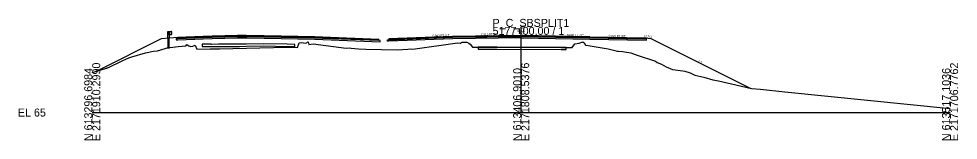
# Model space of a CAD drawing. Extents: x -26 to 1303, y -3010 to 12023.
# Drawn here: x -25.7 to 302.8, y 2990.3 to 3032.8 of the extents above; entities that cross this region are included whole.
import ezdxf

# ---------------------------------------------------------------- set-up
doc = ezdxf.new("R2010")
doc.units = 0
for name, color, linetype in [('RD_GPK_XS_Cell', 7, 'Continuous'), ('RD_PD_Final_TrvlWay', 7, 'Continuous'), ('RD_XS_Base', 7, 'Continuous'), ('RD_XS_ExGround', 7, 'Continuous'), ('RD_XS_ExPaveRet', 7, 'Continuous'), ('RD_XS_GR', 7, 'Continuous'), ('RD_XS_Greenside', 7, 'Continuous'), ('RD_XS_Pave', 7, 'Continuous'), ('RD_XS_PaveOvlay_CP', 7, 'Continuous'), ('RD_XS_TieSlope', 7, 'Continuous'), ('RD_XS_TX_Elev_EX', 7, 'Continuous'), ('RD_XS_TX_Elev_PR', 7, 'Continuous'), ('RD_XS_TX_ShdSlope', 7, 'Continuous'), ('RD_XS_TX_Slope', 7, 'Continuous')]:
    doc.layers.add(name, color=color, linetype=linetype)

msp = doc.modelspace()

# ---------------------------------------------------------------- linework, layer by layer
at = {"layer": 'RD_GPK_XS_Cell'}
for p, q in [((150, 3000), (150, 3030)), ((0, 3000), (150, 3000)), ((150, 3000), (300, 3000))]:
    msp.add_line(p, q, dxfattribs=at)
at = {"layer": 'RD_PD_Final_TrvlWay'}
for p, q in [((26.94, 3026.03), (26.44, 3025.99)), ((26.44, 3025.99), (26.44, 3022.43)), ((26.94, 3022.43), (26.94, 3026.03))]:
    msp.add_line(p, q, dxfattribs=at)
at = {"layer": 'RD_XS_Base'}
for p, q in [((29.75, 3025.95), (29.38, 3025.93)), ((29.38, 3025.93), (29.38, 3025.8)), ((29.38, 3025.8), (29.38, 3025.43)), ((29.88, 3025.95), (29.75, 3025.95)), ((38.75, 3026.31), (29.88, 3025.95)), ((29.88, 3025.45), (38.75, 3025.81)), ((41.88, 3026.43), (38.75, 3026.31)), ((38.75, 3025.81), (41.88, 3025.93)), ((50.75, 3026.61), (41.88, 3026.43)), ((41.88, 3025.93), (50.75, 3026.11)), ((53.88, 3026.67), (50.75, 3026.61)), ((50.75, 3026.11), (53.88, 3026.17)), ((53.88, 3026.79), (53.88, 3026.83)), ((53.88, 3026.83), (53.88, 3026.66)), ((53.88, 3026.67), (53.88, 3026.79)), ((53.88, 3026.54), (53.88, 3026.67)), ((60.14, 3026.55), (53.88, 3026.67)), ((53.88, 3026.66), (53.88, 3026.17)), ((53.88, 3026.17), (53.88, 3026.54)), ((53.88, 3026.17), (60.14, 3026.05)), ((77.88, 3026.19), (60.14, 3026.55)), ((60.14, 3026.05), (77.88, 3025.69)), ((80.49, 3026.09), (77.88, 3026.19)), ((100.21, 3025.3), (80.49, 3026.09)), ((103.74, 3025.46), (126, 3026.35)), ((126, 3025.85), (103.74, 3024.96)), ((126, 3026.35), (150.01, 3026.66)), ((126, 3026.35), (126, 3026.35)), ((150.01, 3026.16), (126, 3025.85)), ((126, 3025.85), (126, 3025.85)), ((150, 3026.66), (150, 3026.82)), ((150, 3026.82), (150, 3026.82)), ((150, 3026.82), (150, 3026.82)), ((150, 3026.82), (150, 3026.16)), ((150, 3026.66), (150, 3026.66)), ((162, 3026.42), (150, 3026.66)), ((150, 3026.66), (150, 3026.66)), ((150, 3026.66), (150, 3026.16)), ((150, 3026.16), (150, 3026.16)), ((150, 3026.16), (162, 3025.92)), ((174, 3026.18), (162, 3026.42)), ((162, 3026.42), (162, 3026.42)), ((162, 3025.92), (162, 3025.92)), ((162, 3025.92), (174, 3025.68)), ((193.3, 3025.8), (174, 3026.18)), ((174, 3026.18), (174, 3026.18)), ((193.8, 3025.79), (193.3, 3025.8)), ((193.3, 3025.8), (193.3, 3025.8)), ((193.8, 3025.29), (193.8, 3025.79)), ((193.8, 3025.79), (193.8, 3025.79)), ((29.38, 3025.43), (29.75, 3025.45)), ((29.75, 3025.45), (29.88, 3025.45)), ((77.88, 3025.69), (80.62, 3025.58)), ((80.62, 3025.58), (100.71, 3024.78)), ((100.34, 3025.29), (100.21, 3025.3)), ((100.71, 3025.28), (100.34, 3025.29)), ((100.71, 3025.15), (100.71, 3025.28)), ((100.71, 3024.78), (100.71, 3025.15)), ((103.24, 3025.44), (103.74, 3025.46)), ((103.24, 3024.94), (103.24, 3025.44)), ((103.24, 3025.44), (103.24, 3025.44)), ((103.74, 3024.96), (103.24, 3024.94)), ((103.24, 3024.94), (103.24, 3024.94)), ((103.24, 3024.94), (103.24, 3024.94)), ((103.74, 3025.46), (103.74, 3025.46)), ((103.74, 3024.96), (103.74, 3024.96)), ((174, 3025.68), (174, 3025.68)), ((174, 3025.68), (193.8, 3025.29))]:
    msp.add_line(p, q, dxfattribs=at)
at = {"layer": 'RD_XS_ExGround'}
msp.add_lwpolyline([(0, 3014.08), (4.65, 3015.43), (5.02, 3015.52), (5.09, 3015.55), (5.24, 3015.64), (5.45, 3015.7), (10.75, 3018.23), (12.84, 3019.16), (13.52, 3019.4), (13.83, 3019.51), (18.57, 3020.96), (21.41, 3021.47), (22.76, 3021.64), (25.49, 3022.44), (26.17, 3022.68), (29.08, 3023.06), (30.02, 3023.11), (32.83, 3023.34), (32.86, 3023.46), (33.13, 3023.79), (33.77, 3023.4), (34.47, 3023.08), (35.18, 3023.19), (36, 3023.59), (36.62, 3022.23), (41.25, 3022.34), (42.12, 3022.34), (44.54, 3022.33), (68.1, 3022.92), (70.89, 3022.85), (71.83, 3022.83), (72.33, 3024.47), (73.09, 3024.48), (74.65, 3024.34), (75.55, 3024.74), (75.74, 3023.81), (77.2, 3024.04), (88.77, 3022.6), (89.85, 3022.63), (90.6, 3022.54), (93.1, 3022.37), (95.69, 3022.14), (106.62, 3021.94), (110.36, 3022.15), (111.14, 3022.26), (112.1, 3022.21), (127.78, 3024.42), (128.61, 3024.35), (128.77, 3024.35), (128.81, 3024.35), (128.9, 3024.29), (129.14, 3024.56), (129.34, 3024.63), (129.75, 3024.66), (130.95, 3024.6), (131.42, 3024.43), (131.67, 3024.26), (132.14, 3023.93), (132.94, 3022.95), (137.76, 3022.92), (138.6, 3022.93), (141.57, 3022.95), (163.96, 3022.81), (167, 3022.82), (167.86, 3022.82), (168.77, 3024.11), (170.33, 3024.26), (171.51, 3024.8), (171.98, 3024.45), (172.52, 3023.57), (173.46, 3023.52), (180.45, 3022.3), (183.74, 3021.55), (184.04, 3021.55), (185.38, 3021.41), (186.08, 3021.22), (188.35, 3020.92), (190.59, 3020.13), (197.03, 3017.94), (197.58, 3017.53), (199.12, 3016.94), (200.7, 3015.96), (202.93, 3015.05), (206.5, 3014.58), (207.28, 3014.53), (209.12, 3013.9), (210.7, 3013.13), (213.87, 3012.43), (217.03, 3011.47), (219.03, 3011.05), (220.5, 3010.76), (223.51, 3010.03), (230.53, 3008.47), (233.64, 3008.15), (242.25, 3007.29), (300, 3001.43)], dxfattribs=at)
at = {"layer": 'RD_XS_ExPaveRet'}
for points in [[(68.2, 3023.92), (59.95, 3024.11), (53.83, 3023.96), (51.54, 3023.91), (44.1, 3023.92), (41.81, 3023.86), (41.61, 3023.92), (38.92, 3023.92), (38.47, 3023.91), (38.47, 3023.37), (38.47, 3023.16), (38.92, 3023.17), (41.61, 3023.17), (41.81, 3023.11), (44.1, 3023.17), (51.54, 3023.16), (53.83, 3023.21), (59.95, 3023.36), (68.2, 3023.17), (70.85, 3023.11), (70.85, 3023.32), (70.85, 3023.86), (68.2, 3023.92)], [(68.2, 3023.92), (59.95, 3024.11), (53.83, 3023.96), (51.54, 3023.91), (44.1, 3023.92), (41.81, 3023.86), (41.61, 3023.92), (38.92, 3023.92), (38.47, 3023.91), (38.47, 3023.37), (38.47, 3023.16), (38.92, 3023.17), (41.61, 3023.17), (41.81, 3023.11), (44.1, 3023.17), (51.54, 3023.16), (53.83, 3023.21), (59.95, 3023.36), (68.2, 3023.17), (70.85, 3023.11), (70.85, 3023.32), (70.85, 3023.86), (68.2, 3023.92)], [(163.96, 3022.81), (163.96, 3022.81), (141.57, 3022.95), (141.57, 3022.95), (141.57, 3022.95), (138.6, 3022.93), (137.76, 3022.92), (137.76, 3022.92), (134.92, 3022.94), (134.92, 3022.94), (134.92, 3022.94), (134.92, 3022.19), (134.92, 3022.19), (137.76, 3022.17), (137.76, 3022.17), (138.6, 3022.18), (141.57, 3022.2), (141.57, 3022.2), (141.57, 3022.2), (163.96, 3022.06), (163.96, 3022.06), (163.96, 3022.06), (165.68, 3022.07), (165.68, 3022.82), (165.68, 3022.82), (163.96, 3022.81), (163.96, 3022.81)], [(163.96, 3022.81), (141.57, 3022.95), (138.6, 3022.93), (137.76, 3022.92), (134.92, 3022.94), (134.92, 3022.19), (137.76, 3022.17), (138.6, 3022.18), (141.57, 3022.2), (163.96, 3022.06), (165.68, 3022.07), (165.68, 3022.82), (163.96, 3022.81)]]:
    msp.add_lwpolyline(points, dxfattribs=at)
at = {"layer": 'RD_XS_GR'}
for p, q in [((26.44, 3025.99), (26.44, 3028.43)), ((26.44, 3028.43), (26.69, 3028.43)), ((26.94, 3026.03), (26.44, 3025.99)), ((26.69, 3028.43), (26.94, 3028.43)), ((26.94, 3028.43), (26.94, 3026.03)), ((26.94, 3027.26), (26.94, 3028.43)), ((26.94, 3028.43), (27.61, 3028.43)), ((27.61, 3027.26), (26.94, 3027.26)), ((27.61, 3028.43), (27.61, 3027.26)), ((27.68, 3028.35), (27.61, 3028.43)), ((27.61, 3028.43), (27.61, 3028.12)), ((27.61, 3028.12), (27.61, 3027.26)), ((27.61, 3027.85), (27.81, 3028.06)), ((27.68, 3027.77), (27.61, 3027.85)), ((27.61, 3027.26), (27.81, 3027.48)), ((27.88, 3028.14), (27.68, 3028.35)), ((27.88, 3027.55), (27.68, 3027.77)), ((27.81, 3028.06), (27.88, 3028.14)), ((27.81, 3027.48), (27.88, 3027.55))]:
    msp.add_line(p, q, dxfattribs=at)
at = {"layer": 'RD_XS_Greenside'}
for p, q in [((24.13, 3025.81), (1.59, 3014.54)), ((195.3, 3025.96), (230.08, 3008.56))]:
    msp.add_line(p, q, dxfattribs=at)
at = {"layer": 'RD_XS_Pave'}
for p, q in [((38.75, 3026.62), (29.88, 3026.27)), ((38.75, 3026.46), (29.88, 3026.11)), ((29.88, 3026.11), (38.75, 3026.46)), ((29.88, 3025.95), (38.75, 3026.31)), ((29.88, 3026.27), (29.88, 3026.23)), ((29.88, 3026.23), (29.88, 3026.11)), ((29.88, 3026.11), (29.88, 3026.07)), ((29.88, 3026.07), (29.88, 3025.95)), ((41.88, 3026.75), (38.75, 3026.62)), ((41.88, 3026.59), (38.75, 3026.46)), ((38.75, 3026.46), (41.88, 3026.59)), ((38.75, 3026.31), (41.88, 3026.43)), ((50.75, 3026.93), (41.88, 3026.75)), ((50.75, 3026.77), (41.88, 3026.59)), ((41.88, 3026.59), (50.75, 3026.77)), ((41.88, 3026.43), (50.75, 3026.61)), ((53.88, 3026.99), (50.75, 3026.93)), ((53.88, 3026.83), (50.75, 3026.77)), ((50.75, 3026.77), (53.88, 3026.83)), ((50.75, 3026.61), (53.88, 3026.67)), ((60.14, 3026.86), (53.88, 3026.99)), ((53.88, 3026.79), (53.88, 3026.83)), ((53.88, 3026.83), (60.14, 3026.7)), ((60.14, 3026.7), (53.88, 3026.83)), ((53.88, 3026.83), (53.88, 3026.79)), ((53.88, 3026.67), (53.88, 3026.79)), ((53.88, 3026.79), (53.88, 3026.67)), ((53.88, 3026.67), (60.14, 3026.55)), ((77.88, 3026.51), (60.14, 3026.86)), ((60.14, 3026.7), (77.88, 3026.35)), ((77.88, 3026.35), (60.14, 3026.7)), ((60.14, 3026.55), (77.88, 3026.19)), ((80.49, 3026.4), (77.88, 3026.51)), ((77.88, 3026.35), (80.49, 3026.25)), ((80.49, 3026.25), (77.88, 3026.35)), ((77.88, 3026.19), (80.49, 3026.09)), ((100.21, 3025.62), (80.49, 3026.4)), ((80.49, 3026.25), (100.21, 3025.46)), ((100.21, 3025.46), (80.49, 3026.25)), ((80.49, 3026.09), (100.21, 3025.3)), ((126, 3026.67), (103.74, 3025.78)), ((126, 3026.51), (103.74, 3025.62)), ((103.74, 3025.62), (126, 3026.51)), ((103.74, 3025.46), (126, 3026.35)), ((150, 3026.98), (126, 3026.67)), ((150, 3026.82), (126, 3026.51)), ((126, 3026.51), (150, 3026.82)), ((126, 3026.67), (126, 3026.67)), ((126, 3026.51), (126, 3026.51)), ((126, 3026.51), (126, 3026.51)), ((126, 3026.35), (126, 3026.35)), ((126.01, 3026.35), (150.01, 3026.66)), ((162, 3026.74), (150, 3026.98)), ((150, 3026.98), (150, 3026.98)), ((150, 3026.66), (150, 3026.82)), ((150, 3026.82), (150, 3026.82)), ((150, 3026.82), (150, 3026.82)), ((150, 3026.82), (162, 3026.58)), ((162, 3026.58), (150, 3026.82)), ((150, 3026.82), (150, 3026.82)), ((150, 3026.82), (150, 3026.82)), ((150, 3026.82), (150, 3026.66)), ((150, 3026.66), (150, 3026.66)), ((150, 3026.66), (162, 3026.42)), ((174, 3026.5), (162, 3026.74)), ((162, 3026.74), (162, 3026.74)), ((162, 3026.58), (162, 3026.58)), ((162, 3026.58), (174, 3026.34)), ((174, 3026.34), (162, 3026.58)), ((162, 3026.58), (162, 3026.58)), ((162, 3026.42), (162, 3026.42)), ((162, 3026.42), (174, 3026.18)), ((174, 3026.5), (193.3, 3026.12)), ((174, 3026.5), (174, 3026.5)), ((174, 3026.34), (174, 3026.34)), ((174, 3026.34), (193.3, 3025.96)), ((193.3, 3025.96), (174, 3026.34)), ((174, 3026.34), (174, 3026.34)), ((174, 3026.18), (193.3, 3025.8)), ((174, 3026.18), (174, 3026.18)), ((193.3, 3025.96), (193.3, 3026.12)), ((193.3, 3026.12), (193.3, 3026.12)), ((193.3, 3025.8), (193.3, 3025.96)), ((193.3, 3025.96), (193.3, 3025.96)), ((100.21, 3025.57), (100.21, 3025.62)), ((100.21, 3025.46), (100.21, 3025.57)), ((100.21, 3025.42), (100.21, 3025.46)), ((100.21, 3025.3), (100.21, 3025.42)), ((103.74, 3025.78), (103.74, 3025.78)), ((103.74, 3025.78), (103.74, 3025.62)), ((103.74, 3025.62), (103.74, 3025.62)), ((103.74, 3025.62), (103.74, 3025.46)), ((103.74, 3025.62), (103.74, 3025.62)), ((103.74, 3025.62), (103.74, 3025.62)), ((103.74, 3025.46), (103.74, 3025.46)), ((103.74, 3025.46), (103.74, 3025.46))]:
    msp.add_line(p, q, dxfattribs=at)
at = {"layer": 'RD_XS_PaveOvlay_CP'}
for p, q in [((29.88, 3026.27), (41.88, 3026.75)), ((41.88, 3026.75), (53.88, 3026.99)), ((53.88, 3026.99), (77.88, 3026.51)), ((77.88, 3026.51), (100.21, 3025.62)), ((126, 3026.67), (103.74, 3025.78)), ((150, 3026.98), (126, 3026.67)), ((126, 3026.67), (126, 3026.67)), ((162, 3026.74), (150, 3026.98)), ((150, 3026.98), (150, 3026.98)), ((174, 3026.5), (162, 3026.74)), ((162, 3026.74), (162, 3026.74)), ((174, 3026.5), (193.3, 3026.12)), ((174, 3026.5), (174, 3026.5)), ((103.74, 3025.78), (103.74, 3025.78))]:
    msp.add_line(p, q, dxfattribs=at)
at = {"layer": 'RD_XS_TieSlope'}
for p, q in [((29.88, 3026.27), (24.13, 3025.81)), ((193.3, 3026.12), (195.3, 3025.96))]:
    msp.add_line(p, q, dxfattribs=at)

# ---------------------------------------------------------------- texts
at = {"layer": 'RD_GPK_XS_Cell'}
for s, p in [('P_C_SBSPLIT1', (140, 3030)), ('5177+00.00 / 1', (140, 3027.2)), ('EL 65', (-26, 2998.6))]:
    msp.add_text(s, height=2.8, dxfattribs=at).set_placement(p)
for s, p in [('E 2171910.2990', (2.8, 2990)), ('E 2171808.5376', (152.8, 2990)), ('E 2171706.7762', (302.8, 2990)), ('N 613296.6984', (0, 2990)), ('N 613406.9010', (150, 2990)), ('N 613517.1036', (300, 2990))]:
    msp.add_text(s, height=2.8, rotation=90, dxfattribs=at).set_placement(p)
at = {"layer": 'RD_XS_TX_Elev_EX'}
msp.add_text('88.61', height=0.6, rotation=90, dxfattribs=at).set_placement((149.74, 3027.63))
at = {"layer": 'RD_XS_TX_Elev_PR'}
msp.add_text('91.98', height=1, rotation=90, dxfattribs=at).set_placement((151.17, 3027.28))
at = {"layer": 'RD_XS_TX_ShdSlope'}
msp.add_text('12.5:1', height=0.75, rotation=355.4261, dxfattribs=at).set_placement((192.84, 3026.43))
at = {"layer": 'RD_XS_TX_Slope'}
for s, rotation, p in [('0.040 FT./FT.', 2.2906, (118.94, 3026.49)), ('0.013 FT./FT.', 1.1524, (135.94, 3027)), ('0.020 FT./FT.', 358.8542, (165.94, 3026.76)), ('0.020 FT./FT.', 358.8542, (180.59, 3026.47)), ('2:1', 333.4349, (211.8, 3017.77))]:
    msp.add_text(s, height=0.75, rotation=rotation, dxfattribs=at).set_placement(p)

doc.saveas('drawing.dxf')
